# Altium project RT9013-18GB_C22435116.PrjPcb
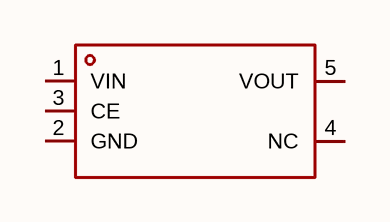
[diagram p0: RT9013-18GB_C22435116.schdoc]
1 sheet, 1 parts. Net scope: global (net labels, ports and power ports of the same name join across sheets).

## Sheet RT9013-18GB_C22435116.schdoc
size 127 x 101 mm

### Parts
U?  rt9013-18gb_c22435116  [SOT-23-5_L3.0-W1.7-P0.95-LS2.8-BR]  (value not drawn)

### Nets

Not connected (* = marked no-connect by the designer): U? 1(VIN) 2(GND) 3(CE) 4(NC) 5(VOUT)

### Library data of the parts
U? = rt9013-18gb_c22435116: 输出极性:正极;工作电压:7V;输出电压:1.8V;输出电流:500mA;电源纹波抑制比(PSRR):70dB@(1kHz);输出类型:固定;; Manufacturer: TECH PUBLIC(台舟); AddInBom: yes; ModelId: 0a2a1b8f50944f73965918ad6e5fe167; ModelName: SOT-23-5_L2.9-W1.6-H1.1-LS2.8-P0.95; ModelTransform: 114.173,109.636,0,180,0,0,0,0,0; Output Configuration: 正极; Voltage - Supply: 7V; Output Voltage: 1.8V; Output Current: 500mA; standby current: 60uA; Noise: 50uVrms; Output Type: 固定; Number of Outputs: 1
